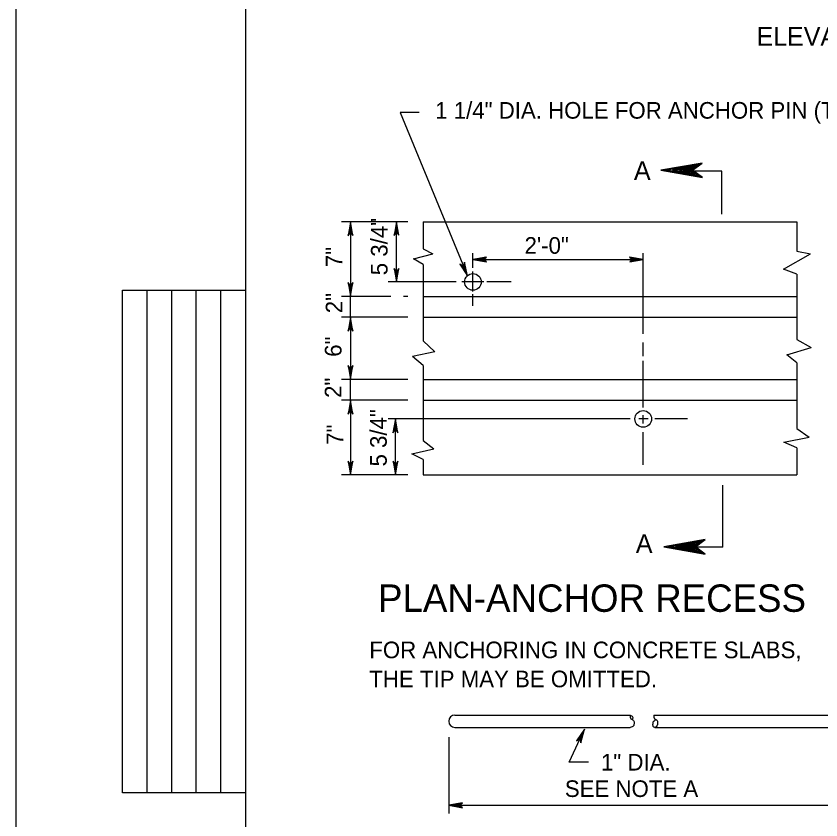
# Model space of a CAD drawing. Extents: x 499866 to 500993, y 499985 to 500645.
# Drawn here: x 499944.8 to 500138.5, y 500259.3 to 500452.8 of the extents above; entities that cross this region are included whole.
import ezdxf

# ---------------------------------------------------------------- set-up
doc = ezdxf.new("R2010")
doc.units = 0
for name, color, linetype in [('1', 7, 'Continuous'), ('24', 7, 'Continuous'), ('41', 7, 'Continuous'), ('5', 7, 'Continuous')]:
    doc.layers.add(name, color=color, linetype=linetype)

msp = doc.modelspace()

# ---------------------------------------------------------------- linework, layer by layer
at = {"layer": '1'}
for p, q in [((500000, 500630), (500000, 500000)), ((499970.47, 500265.75), (499970.47, 500386.81)), ((499970.47, 500386.81), (500000, 500386.81)), ((499976.38, 500265.75), (499976.38, 500386.81)), ((499982.28, 500265.75), (499982.28, 500386.81)), ((499988.19, 500265.75), (499988.19, 500386.81)), ((499994.09, 500265.75), (499994.09, 500386.81)), ((500000, 500265.75), (499970.47, 500265.75))]:
    msp.add_line(p, q, dxfattribs=at)
at = {"layer": '24'}
for points in [[(500025.31, 500403.26), (500024.71, 500399.91), (500025.31, 500400.71), (500025.89, 500399.93), (500025.31, 500403.26), (500025.31, 500403.04), (500024.76, 500400), (500025.31, 500400.77), (500025.84, 500400.06), (500025.32, 500402.92), (500025.31, 500402.8), (500024.85, 500400.21), (500025.31, 500400.79), (500025.77, 500400.19), (500025.31, 500402.75), (500025.32, 500402.64), (500024.91, 500400.37), (500025.31, 500400.81), (500025.72, 500400.36), (500025.32, 500402.32), (500025.32, 500402.13), (500025, 500400.54), (500025.3, 500400.85), (500025.63, 500400.51), (500025.31, 500402.1), (500025.3, 500401.92), (500025.09, 500400.72), (500025.32, 500400.95), (500025.55, 500400.7), (500025.31, 500401.75), (500025.29, 500401.58), (500025.15, 500400.87), (500025.31, 500400.98), (500025.49, 500400.79), (500025.31, 500401.5), (500025.2, 500401.03), (500025.32, 500401.1), (500025.45, 500400.89), (500025.32, 500401.38), (500025.25, 500401.07), (500025.35, 500401.2), (500025.41, 500401.05), (500025.31, 500401.2), (500025.3, 500401.12)], [(500036.36, 500403.26), (500035.78, 500399.98), (500036.36, 500400.77), (500036.93, 500400), (500036.36, 500403.26), (500036.37, 500403.04), (500035.83, 500400.08), (500036.37, 500400.83), (500036.89, 500400.13), (500036.38, 500402.92), (500036.36, 500402.81), (500035.91, 500400.27), (500036.37, 500400.84), (500036.81, 500400.26), (500036.36, 500402.76), (500036.38, 500402.66), (500035.98, 500400.44), (500036.36, 500400.87), (500036.76, 500400.43), (500036.38, 500402.34), (500036.38, 500402.15), (500036.06, 500400.6), (500036.35, 500400.9), (500036.68, 500400.58), (500036.36, 500402.12), (500036.35, 500401.95), (500036.15, 500400.78), (500036.38, 500401), (500036.6, 500400.76), (500036.36, 500401.79), (500036.35, 500401.62), (500036.21, 500400.92), (500036.37, 500401.03), (500036.55, 500400.84), (500036.36, 500401.54), (500036.25, 500401.08), (500036.38, 500401.14), (500036.51, 500400.94), (500036.38, 500401.42), (500036.3, 500401.12), (500036.4, 500401.25), (500036.46, 500401.1), (500036.37, 500401.25), (500036.35, 500401.17)], [(500036.36, 500403.26), (500035.78, 500399.98), (500036.36, 500400.77), (500036.93, 500400), (500036.36, 500403.26), (500036.37, 500403.04), (500035.83, 500400.08), (500036.37, 500400.83), (500036.89, 500400.13), (500036.38, 500402.92), (500036.36, 500402.81), (500035.91, 500400.27), (500036.37, 500400.84), (500036.81, 500400.26), (500036.36, 500402.76), (500036.38, 500402.66), (500035.98, 500400.44), (500036.36, 500400.87), (500036.76, 500400.43), (500036.38, 500402.34), (500036.38, 500402.15), (500036.06, 500400.6), (500036.35, 500400.9), (500036.68, 500400.58), (500036.36, 500402.12), (500036.35, 500401.95), (500036.15, 500400.78), (500036.38, 500401), (500036.6, 500400.76), (500036.36, 500401.79), (500036.35, 500401.62), (500036.21, 500400.92), (500036.37, 500401.03), (500036.55, 500400.84), (500036.36, 500401.54), (500036.25, 500401.08), (500036.38, 500401.14), (500036.51, 500400.94), (500036.38, 500401.42), (500036.3, 500401.12), (500036.4, 500401.25), (500036.46, 500401.1), (500036.37, 500401.25), (500036.35, 500401.17)], [(500053.42, 500390.27), (500052.71, 500393.52), (500052.47, 500392.58), (500051.65, 500393.07), (500053.42, 500390.27), (500053.33, 500390.47), (500052.7, 500393.42), (500052.49, 500392.52), (500051.75, 500392.96), (500053.28, 500390.58), (500053.25, 500390.68), (500052.7, 500393.2), (500052.5, 500392.5), (500051.86, 500392.88), (500053.23, 500390.73), (500053.18, 500390.82), (500052.7, 500393.03), (500052.51, 500392.48), (500051.97, 500392.74), (500053.06, 500391.12), (500052.99, 500391.29), (500052.69, 500392.85), (500052.53, 500392.46), (500052.11, 500392.63), (500052.99, 500391.32), (500052.93, 500391.49), (500052.67, 500392.65), (500052.55, 500392.35), (500052.25, 500392.49), (500052.86, 500391.63), (500052.81, 500391.79), (500052.67, 500392.49), (500052.57, 500392.33), (500052.33, 500392.44), (500052.77, 500391.87), (500052.69, 500392.33), (500052.6, 500392.22), (500052.41, 500392.36), (500052.71, 500391.97), (500052.66, 500392.27), (500052.62, 500392.12), (500052.51, 500392.23), (500052.65, 500392.13), (500052.63, 500392.21)], [(500054.77, 500394.19), (500058.05, 500393.61), (500057.27, 500394.19), (500058.03, 500394.76), (500054.77, 500394.19), (500054.99, 500394.19), (500057.96, 500393.65), (500057.21, 500394.19), (500057.9, 500394.71), (500055.11, 500394.2), (500055.22, 500394.19), (500057.76, 500393.74), (500057.19, 500394.19), (500057.77, 500394.64), (500055.27, 500394.19), (500055.38, 500394.2), (500057.6, 500393.8), (500057.17, 500394.19), (500057.61, 500394.59), (500055.69, 500394.2), (500055.88, 500394.2), (500057.43, 500393.88), (500057.13, 500394.18), (500057.46, 500394.5), (500055.91, 500394.19), (500056.09, 500394.18), (500057.25, 500393.98), (500057.03, 500394.2), (500057.27, 500394.43), (500056.25, 500394.19), (500056.41, 500394.17), (500057.11, 500394.04), (500057, 500394.19), (500057.19, 500394.37), (500056.5, 500394.19), (500056.95, 500394.08), (500056.89, 500394.2), (500057.09, 500394.33), (500056.61, 500394.2), (500056.91, 500394.13), (500056.79, 500394.23), (500056.93, 500394.29), (500056.79, 500394.19), (500056.86, 500394.18)], [(500095.74, 500394.19), (500092.47, 500394.77), (500093.25, 500394.19), (500092.49, 500393.62), (500095.74, 500394.19), (500095.53, 500394.18), (500092.56, 500394.72), (500093.31, 500394.18), (500092.62, 500393.66), (500095.41, 500394.17), (500095.3, 500394.19), (500092.76, 500394.64), (500093.33, 500394.18), (500092.74, 500393.74), (500095.25, 500394.19), (500095.14, 500394.17), (500092.92, 500394.57), (500093.35, 500394.19), (500092.91, 500393.79), (500094.82, 500394.17), (500094.64, 500394.17), (500093.09, 500394.49), (500093.39, 500394.2), (500093.06, 500393.87), (500094.61, 500394.19), (500094.43, 500394.2), (500093.26, 500394.4), (500093.49, 500394.17), (500093.24, 500393.95), (500094.27, 500394.19), (500094.11, 500394.2), (500093.4, 500394.34), (500093.52, 500394.18), (500093.33, 500394), (500094.02, 500394.19), (500093.56, 500394.3), (500093.63, 500394.17), (500093.43, 500394.04), (500093.91, 500394.17), (500093.61, 500394.25), (500093.73, 500394.15), (500093.59, 500394.09), (500093.73, 500394.18), (500093.66, 500394.2)], [(500036.36, 500388.77), (500036.94, 500392.04), (500036.36, 500391.26), (500035.79, 500392.03), (500036.36, 500388.77), (500036.36, 500388.99), (500036.9, 500391.95), (500036.36, 500391.2), (500035.84, 500391.89), (500036.35, 500389.1), (500036.36, 500389.21), (500036.81, 500391.75), (500036.36, 500391.18), (500035.91, 500391.77), (500036.36, 500389.26), (500036.35, 500389.37), (500036.75, 500391.59), (500036.36, 500391.16), (500035.96, 500391.6), (500036.35, 500389.69), (500036.35, 500389.87), (500036.67, 500391.43), (500036.37, 500391.12), (500036.05, 500391.45), (500036.36, 500389.91), (500036.37, 500390.08), (500036.57, 500391.25), (500036.35, 500391.02), (500036.12, 500391.27), (500036.36, 500390.24), (500036.38, 500390.41), (500036.51, 500391.11), (500036.36, 500390.99), (500036.18, 500391.18), (500036.36, 500390.49), (500036.47, 500390.95), (500036.35, 500390.88), (500036.22, 500391.08), (500036.35, 500390.61), (500036.42, 500390.91), (500036.32, 500390.78), (500036.26, 500390.93), (500036.36, 500390.78), (500036.37, 500390.86)], [(500025.31, 500385.27), (500025.9, 500388.62), (500025.31, 500387.82), (500024.72, 500388.6), (500025.31, 500385.27), (500025.3, 500385.49), (500025.86, 500388.53), (500025.3, 500387.76), (500024.77, 500388.47), (500025.29, 500385.61), (500025.31, 500385.73), (500025.77, 500388.32), (500025.3, 500387.74), (500024.85, 500388.34), (500025.31, 500385.78), (500025.29, 500385.89), (500025.7, 500388.16), (500025.31, 500387.72), (500024.9, 500388.17), (500025.29, 500386.21), (500025.29, 500386.4), (500025.62, 500387.99), (500025.32, 500387.68), (500024.98, 500388.02), (500025.31, 500386.43), (500025.32, 500386.61), (500025.52, 500387.81), (500025.29, 500387.58), (500025.06, 500387.83), (500025.31, 500386.78), (500025.32, 500386.95), (500025.46, 500387.66), (500025.3, 500387.55), (500025.12, 500387.74), (500025.31, 500387.03), (500025.42, 500387.5), (500025.29, 500387.43), (500025.16, 500387.64), (500025.29, 500387.15), (500025.37, 500387.46), (500025.27, 500387.33), (500025.21, 500387.48), (500025.3, 500387.33), (500025.32, 500387.41)], [(500025.31, 500380.28), (500024.71, 500376.93), (500025.31, 500377.73), (500025.89, 500376.94), (500025.31, 500380.28), (500025.31, 500380.05), (500024.76, 500377.02), (500025.31, 500377.79), (500025.84, 500377.08), (500025.32, 500379.93), (500025.31, 500379.82), (500024.85, 500377.22), (500025.31, 500377.81), (500025.77, 500377.21), (500025.31, 500379.77), (500025.32, 500379.66), (500024.91, 500377.39), (500025.31, 500377.83), (500025.72, 500377.38), (500025.32, 500379.34), (500025.32, 500379.15), (500025, 500377.56), (500025.3, 500377.87), (500025.63, 500377.53), (500025.31, 500379.11), (500025.3, 500378.93), (500025.09, 500377.74), (500025.32, 500377.97), (500025.55, 500377.72), (500025.31, 500378.77), (500025.29, 500378.6), (500025.15, 500377.88), (500025.31, 500378), (500025.49, 500377.81), (500025.31, 500378.51), (500025.2, 500378.04), (500025.32, 500378.11), (500025.45, 500377.91), (500025.32, 500378.4), (500025.25, 500378.09), (500025.35, 500378.22), (500025.41, 500378.07), (500025.31, 500378.22), (500025.3, 500378.14)], [(500025.31, 500365.29), (500025.9, 500368.64), (500025.31, 500367.84), (500024.72, 500368.62), (500025.31, 500365.29), (500025.3, 500365.51), (500025.86, 500368.54), (500025.3, 500367.77), (500024.77, 500368.48), (500025.29, 500365.63), (500025.31, 500365.74), (500025.77, 500368.34), (500025.3, 500367.76), (500024.85, 500368.36), (500025.31, 500365.79), (500025.29, 500365.9), (500025.7, 500368.17), (500025.31, 500367.73), (500024.9, 500368.18), (500025.29, 500366.23), (500025.29, 500366.42), (500025.62, 500368.01), (500025.32, 500367.7), (500024.98, 500368.03), (500025.31, 500366.45), (500025.32, 500366.63), (500025.52, 500367.82), (500025.29, 500367.59), (500025.06, 500367.84), (500025.31, 500366.79), (500025.32, 500366.96), (500025.46, 500367.68), (500025.3, 500367.56), (500025.12, 500367.76), (500025.31, 500367.05), (500025.42, 500367.52), (500025.29, 500367.45), (500025.16, 500367.66), (500025.29, 500367.17), (500025.37, 500367.47), (500025.27, 500367.35), (500025.21, 500367.49), (500025.3, 500367.35), (500025.32, 500367.42)], [(500025.31, 500360.29), (500024.71, 500356.94), (500025.31, 500357.74), (500025.89, 500356.96), (500025.31, 500360.29), (500025.31, 500360.07), (500024.76, 500357.03), (500025.31, 500357.8), (500025.84, 500357.09), (500025.32, 500359.95), (500025.31, 500359.84), (500024.85, 500357.24), (500025.31, 500357.82), (500025.77, 500357.22), (500025.31, 500359.79), (500025.32, 500359.67), (500024.91, 500357.4), (500025.31, 500357.84), (500025.72, 500357.39), (500025.32, 500359.35), (500025.32, 500359.16), (500025, 500357.57), (500025.3, 500357.88), (500025.63, 500357.55), (500025.31, 500359.13), (500025.3, 500358.95), (500025.09, 500357.75), (500025.32, 500357.98), (500025.55, 500357.73), (500025.31, 500358.78), (500025.29, 500358.62), (500025.15, 500357.9), (500025.31, 500358.02), (500025.49, 500357.82), (500025.31, 500358.53), (500025.2, 500358.06), (500025.32, 500358.13), (500025.45, 500357.92), (500025.32, 500358.41), (500025.25, 500358.1), (500025.35, 500358.23), (500025.41, 500358.08), (500025.31, 500358.23), (500025.3, 500358.15)], [(500036.12, 500355.79), (500035.52, 500352.44), (500036.12, 500353.24), (500036.7, 500352.46), (500036.12, 500355.79), (500036.12, 500355.57), (500035.57, 500352.54), (500036.12, 500353.31), (500036.65, 500352.6), (500036.13, 500355.45), (500036.12, 500355.34), (500035.65, 500352.74), (500036.12, 500353.32), (500036.58, 500352.72), (500036.12, 500355.29), (500036.13, 500355.18), (500035.72, 500352.91), (500036.12, 500353.35), (500036.52, 500352.9), (500036.13, 500354.85), (500036.13, 500354.67), (500035.81, 500353.07), (500036.11, 500353.38), (500036.44, 500353.05), (500036.12, 500354.63), (500036.11, 500354.45), (500035.9, 500353.26), (500036.13, 500353.49), (500036.36, 500353.24), (500036.12, 500354.29), (500036.1, 500354.12), (500035.96, 500353.4), (500036.12, 500353.52), (500036.3, 500353.32), (500036.12, 500354.03), (500036, 500353.56), (500036.13, 500353.63), (500036.26, 500353.43), (500036.13, 500353.91), (500036.06, 500353.61), (500036.16, 500353.74), (500036.22, 500353.59), (500036.12, 500353.73), (500036.11, 500353.66)], [(500025.31, 500342.3), (500025.9, 500345.65), (500025.31, 500344.85), (500024.72, 500345.64), (500025.31, 500342.3), (500025.3, 500342.53), (500025.86, 500345.56), (500025.3, 500344.79), (500024.77, 500345.5), (500025.29, 500342.65), (500025.31, 500342.76), (500025.77, 500345.36), (500025.3, 500344.77), (500024.85, 500345.37), (500025.31, 500342.81), (500025.29, 500342.92), (500025.7, 500345.19), (500025.31, 500344.75), (500024.9, 500345.2), (500025.29, 500343.24), (500025.29, 500343.43), (500025.62, 500345.02), (500025.32, 500344.71), (500024.98, 500345.05), (500025.31, 500343.47), (500025.32, 500343.65), (500025.52, 500344.84), (500025.29, 500344.61), (500025.06, 500344.86), (500025.31, 500343.81), (500025.32, 500343.98), (500025.46, 500344.7), (500025.3, 500344.58), (500025.12, 500344.77), (500025.31, 500344.07), (500025.42, 500344.53), (500025.29, 500344.47), (500025.16, 500344.67), (500025.29, 500344.18), (500025.37, 500344.49), (500025.27, 500344.36), (500025.21, 500344.51), (500025.3, 500344.36), (500025.32, 500344.44)], [(500036.12, 500342.3), (500036.71, 500345.65), (500036.12, 500344.85), (500035.53, 500345.64), (500036.12, 500342.3), (500036.11, 500342.53), (500036.66, 500345.56), (500036.11, 500344.79), (500035.58, 500345.5), (500036.1, 500342.65), (500036.12, 500342.76), (500036.58, 500345.36), (500036.11, 500344.77), (500035.65, 500345.37), (500036.12, 500342.81), (500036.1, 500342.92), (500036.51, 500345.19), (500036.12, 500344.75), (500035.71, 500345.2), (500036.1, 500343.24), (500036.1, 500343.43), (500036.43, 500345.02), (500036.13, 500344.71), (500035.79, 500345.05), (500036.12, 500343.47), (500036.13, 500343.65), (500036.33, 500344.84), (500036.1, 500344.61), (500035.87, 500344.86), (500036.12, 500343.81), (500036.13, 500343.98), (500036.27, 500344.7), (500036.11, 500344.58), (500035.93, 500344.77), (500036.12, 500344.07), (500036.23, 500344.53), (500036.1, 500344.47), (500035.97, 500344.67), (500036.1, 500344.18), (500036.18, 500344.49), (500036.08, 500344.36), (500036.01, 500344.51), (500036.11, 500344.36), (500036.13, 500344.44)], [(500081.62, 500281.12), (500079.66, 500278.33), (500080.54, 500278.81), (500080.73, 500277.85), (500081.62, 500281.12), (500081.53, 500280.91), (500079.74, 500278.4), (500080.57, 500278.86), (500080.75, 500277.99), (500081.49, 500280.8), (500081.43, 500280.71), (500079.91, 500278.55), (500080.58, 500278.88), (500080.74, 500278.14), (500081.4, 500280.66), (500081.37, 500280.55), (500080.04, 500278.67), (500080.58, 500278.9), (500080.76, 500278.32), (500081.24, 500280.26), (500081.15, 500280.09), (500080.19, 500278.78), (500080.59, 500278.94), (500080.75, 500278.49), (500081.13, 500280.06), (500081.04, 500279.91), (500080.35, 500278.91), (500080.66, 500279.02), (500080.76, 500278.7), (500080.98, 500279.75), (500080.89, 500279.61), (500080.46, 500279.01), (500080.66, 500279.05), (500080.74, 500278.8), (500080.87, 500279.52), (500080.57, 500279.14), (500080.72, 500279.15), (500080.75, 500278.91), (500080.84, 500279.41), (500080.64, 500279.16), (500080.78, 500279.24), (500080.78, 500279.08), (500080.75, 500279.25), (500080.7, 500279.19)], [(500048.93, 500262.78), (500052.28, 500262.19), (500051.48, 500262.78), (500052.27, 500263.36), (500048.93, 500262.78), (500049.16, 500262.79), (500052.19, 500262.23), (500051.42, 500262.79), (500052.13, 500263.32), (500049.28, 500262.8), (500049.39, 500262.78), (500051.99, 500262.32), (500051.4, 500262.79), (500052, 500263.24), (500049.44, 500262.78), (500049.55, 500262.8), (500051.82, 500262.39), (500051.38, 500262.78), (500051.83, 500263.19), (500049.87, 500262.8), (500050.06, 500262.8), (500051.65, 500262.47), (500051.34, 500262.77), (500051.68, 500263.1), (500050.1, 500262.78), (500050.28, 500262.77), (500051.47, 500262.57), (500051.24, 500262.8), (500051.49, 500263.03), (500050.44, 500262.78), (500050.61, 500262.76), (500051.33, 500262.63), (500051.21, 500262.79), (500051.4, 500262.97), (500050.7, 500262.78), (500051.16, 500262.67), (500051.1, 500262.8), (500051.3, 500262.93), (500050.81, 500262.8), (500051.12, 500262.72), (500050.99, 500262.82), (500051.14, 500262.88), (500050.99, 500262.79), (500051.07, 500262.77)]]:
    msp.add_lwpolyline(points, dxfattribs=at)
at = {"layer": '41'}
msp.add_lwpolyline([(499944.83, 500645), (500993, 500645), (500993, 499985), (499944.83, 499985)], close=True, dxfattribs=at)
at = {"layer": '5'}
for p, q in [((500114.7, 500415.41), (500104.71, 500415.41)), ((500114.7, 500405.09), (500114.7, 500415.41)), ((500039.11, 500403.26), (500023.15, 500403.26)), ((500025.31, 500403.26), (500025.31, 500385.27)), ((500036.36, 500388.77), (500036.36, 500403.26)), ((500042.78, 500403.26), (500132.72, 500403.26)), ((500042.78, 500403.26), (500042.78, 500396.74)), ((500132.72, 500403.26), (500132.72, 500396.2)), ((500040.47, 500394.3), (500045.08, 500395.52)), ((500042.78, 500396.74), (500045.08, 500395.52)), ((500054.77, 500392.13), (500054.77, 500395.73)), ((500095.74, 500376.29), (500095.74, 500395.73)), ((500129.48, 500391.86), (500135.99, 500395.52)), ((500132.72, 500396.2), (500135.99, 500395.52)), ((500042.78, 500392.94), (500040.47, 500394.3)), ((500054.77, 500394.19), (500095.74, 500394.19)), ((500042.78, 500392.94), (500042.78, 500374.63)), ((500054.77, 500386.44), (500054.77, 500391.26)), ((500132.72, 500390.64), (500129.48, 500391.86)), ((500132.72, 500390.64), (500132.72, 500374.9)), ((500050.77, 500388.77), (500034.37, 500388.77)), ((500057.39, 500388.77), (500052.07, 500388.77)), ((500063.94, 500388.77), (500058.11, 500388.77)), ((500054.77, 500383.04), (500054.77, 500385.85)), ((500035.04, 500385.27), (500023.15, 500385.27)), ((500025.31, 500380.28), (500025.31, 500385.27)), ((500039.11, 500385.27), (500038.03, 500385.27)), ((500042.78, 500385.27), (500132.72, 500385.27)), ((500039.11, 500380.28), (500023.15, 500380.28)), ((500025.31, 500380.28), (500025.31, 500365.29)), ((500042.78, 500380.28), (500132.72, 500380.28)), ((500042.78, 500374.63), (500045.63, 500371.91)), ((500095.74, 500370.89), (500095.74, 500374.19)), ((500132.72, 500374.9), (500136.13, 500373)), ((500045.63, 500371.91), (500040.2, 500370.83)), ((500130.29, 500371.23), (500136.13, 500373)), ((500042.78, 500368.66), (500040.2, 500370.83)), ((500132.72, 500369.33), (500130.29, 500371.23)), ((500042.78, 500368.66), (500042.78, 500350.61)), ((500095.74, 500358.58), (500095.74, 500369.79)), ((500132.72, 500369.33), (500132.72, 500353.46)), ((500039.11, 500365.29), (500023.15, 500365.29)), ((500025.27, 500360.29), (500025.31, 500365.29)), ((500042.78, 500365.29), (500132.72, 500365.29)), ((500039.11, 500360.29), (500023.15, 500360.29)), ((500025.31, 500360.29), (500025.31, 500342.3)), ((500042.78, 500360.29), (500132.72, 500360.29)), ((500095.74, 500354.68), (500095.74, 500356.68)), ((500092.62, 500355.79), (500034.37, 500355.79)), ((500036.12, 500342.3), (500036.12, 500355.79)), ((500096.92, 500355.79), (500094.72, 500355.79)), ((500106.41, 500355.79), (500098.53, 500355.79)), ((500095.74, 500344.78), (500095.74, 500352.58)), ((500132.72, 500353.46), (500135.72, 500351.42)), ((500042.78, 500350.61), (500045.36, 500348.58)), ((500129.61, 500350.2), (500135.72, 500351.42)), ((500132.72, 500348.85), (500129.61, 500350.2)), ((500132.72, 500348.85), (500132.72, 500342.3)), ((500040.06, 500347.35), (500045.36, 500348.58)), ((500042.78, 500346), (500040.06, 500347.35)), ((500042.78, 500346), (500042.78, 500342.3)), ((500039.11, 500342.3), (500023.15, 500342.3)), ((500042.78, 500342.3), (500132.72, 500342.3)), ((500114.94, 500324.89), (500114.94, 500339.82)), ((500114.94, 500324.89), (500104.95, 500324.89)), ((500050.43, 500284.51), (500092.64, 500284.51)), ((500098.3, 500284.51), (500143.36, 500284.51)), ((500050.43, 500281.51), (500092.64, 500281.51)), ((500098.52, 500281.51), (500143.36, 500281.51)), ((500048.93, 500279.15), (500048.93, 500260.78)), ((500048.93, 500262.78), (500148.36, 500262.78))]:
    msp.add_line(p, q, dxfattribs=at)
for points in [[(500041.79, 500429.6), (500037.23, 500429.6), (500053.42, 500390.27)], [(500100.02, 500415.64), (500110, 500413.88), (500107.61, 500415.64), (500109.95, 500417.37), (500100.02, 500415.64), (500100.69, 500415.66), (500109.72, 500414.01), (500107.43, 500415.66), (500109.54, 500417.24), (500101.04, 500415.69), (500101.38, 500415.64), (500109.11, 500414.26), (500107.38, 500415.66), (500109.16, 500417.01), (500101.53, 500415.64), (500101.86, 500415.69), (500108.62, 500414.47), (500107.31, 500415.64), (500108.65, 500416.85), (500102.82, 500415.69), (500103.39, 500415.69), (500108.12, 500414.72), (500107.2, 500415.61), (500108.19, 500416.6), (500103.49, 500415.64), (500104.02, 500415.61), (500107.58, 500415), (500106.89, 500415.69), (500107.64, 500416.37), (500104.51, 500415.64), (500105.01, 500415.59), (500107.15, 500415.18), (500106.8, 500415.66), (500107.38, 500416.19), (500105.27, 500415.64), (500106.66, 500415.31), (500106.46, 500415.69), (500107.07, 500416.07), (500105.62, 500415.69), (500106.54, 500415.46), (500106.15, 500415.76), (500106.59, 500415.94), (500106.15, 500415.66), (500106.38, 500415.61)], [(500100.72, 500325.01), (500110.69, 500323.25), (500108.31, 500325.01), (500110.64, 500326.75), (500100.72, 500325.01), (500101.38, 500325.03), (500110.41, 500323.38), (500108.12, 500325.03), (500110.24, 500326.61), (500101.74, 500325.06), (500102.07, 500325.01), (500109.81, 500323.64), (500108.07, 500325.03), (500109.86, 500326.39), (500102.22, 500325.01), (500102.55, 500325.06), (500109.32, 500323.84), (500108, 500325.01), (500109.34, 500326.23), (500103.52, 500325.06), (500104.08, 500325.06), (500108.81, 500324.09), (500107.89, 500324.98), (500108.89, 500325.98), (500104.18, 500325.01), (500104.71, 500324.98), (500108.27, 500324.37), (500107.59, 500325.06), (500108.33, 500325.74), (500105.2, 500325.01), (500105.71, 500324.96), (500107.84, 500324.55), (500107.49, 500325.03), (500108.07, 500325.57), (500105.97, 500325.01), (500107.36, 500324.68), (500107.16, 500325.06), (500107.77, 500325.44), (500106.32, 500325.06), (500107.23, 500324.83), (500106.85, 500325.13), (500107.29, 500325.31), (500106.85, 500325.03), (500107.08, 500324.98)], [(500082.58, 500273.15), (500077.9, 500273.15), (500081.62, 500281.12)]]:
    msp.add_lwpolyline(points, dxfattribs=at)
for centre in [(500054.77, 500388.77), (500095.74, 500355.79)]:
    msp.add_circle(centre, 2, dxfattribs=at)
msp.add_arc((500050.43, 500283.01), 1.5, 90, 270, dxfattribs=at)
for points in [[(500092.64, 500284.51), (500092.8, 500283.63), (500093.28, 500283.36), (500093.55, 500282.67), (500093.5, 500282.19), (500093.39, 500281.87), (500092.64, 500281.51)], [(500092.64, 500284.51), (500093.17, 500284.11), (500093.23, 500283.74), (500093.01, 500283.52)], [(500098.52, 500281.51), (500098.3, 500281.6), (500098.09, 500282.3), (500098.14, 500282.51), (500098.14, 500282.78), (500098.25, 500282.99), (500098.46, 500283.15), (500098.52, 500283.2), (500098.68, 500283.42)], [(500098.3, 500284.51), (500098.46, 500283.63), (500098.94, 500283.36), (500099.21, 500282.67), (500099.16, 500282.19), (500099.05, 500281.87), (500098.52, 500281.51)]]:
    msp.add_spline(points, degree=3, dxfattribs=at)

# ---------------------------------------------------------------- texts
for s, height, p in [('ELEVATION', 4.5, (500123, 500445.63)), ('1 1/4" DIA. HOLE FOR ANCHOR PIN (TYP.)', 4, (500045.69, 500428.08)), ('A', 4.5, (500093.51, 500413.34)), ('2\'-0"', 4, (500067.19, 500395.56)), ('A', 4.5, (500093.97, 500323.53)), ('PLAN-ANCHOR RECESS', 6.6001, (500031.93, 500309.35)), ('FOR ANCHORING IN CONCRETE SLABS,', 4, (500029.83, 500298.19)), ('THE TIP MAY BE OMITTED.', 4, (500029.83, 500291.19)), ('1" DIA.', 4, (500085.58, 500271.15)), ('SEE NOTE A ', 4, (500076.88, 500264.78))]:
    msp.add_text(s, height=height, dxfattribs=at).set_placement(p)
for s, p in [('5 3/4"', (500034.22, 500390.38)), ('7"', (500023.34, 500392.33)), ('2"', (500023.34, 500381.24)), ('6"', (500023.14, 500370.75)), ('2"', (500023.12, 500360.85)), ('5 3/4"', (500034.03, 500344.34)), ('7"', (500023.54, 500349.56))]:
    msp.add_text(s, height=4, rotation=90, dxfattribs=at).set_placement(p)

doc.saveas('drawing.dxf')
